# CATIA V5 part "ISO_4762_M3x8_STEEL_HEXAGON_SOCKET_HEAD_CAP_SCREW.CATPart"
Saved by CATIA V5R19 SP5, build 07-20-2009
Part number: ISO 4762 SCREW M3x8 STEEL HEXAGON SOCKET HEAD CAP
Publications: "Mating Face", "Axis"
Bounding box of the stored display mesh (mm): x -8 to 3, y -2.75 to 2.75, z -2.615 to 2.615
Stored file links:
  Z:\UA\ATLAS\atlascar\ServoPiloto\dir\suportePotenciometro\V2\potenciometro\ISO_4762_M3x8_STEEL_HEXAGON_SOCKET_HEAD_CAP_SCREW.CATPart
  Z:\programs_vbox\Dassault Systemes\B19\intel_a\startup\components\MechanicalStandardParts\EN_Standards\Design_Tables\EN_ISO_4762_HEXAGON_SOCKET_HEAD_CAP_SCREW.txt
  Z:\programs_vbox\Dassault Systemes\B19\intel_a\startup\components\MechanicalStandardParts\ISO_Standards\Design_Tables\ISO_4762_HEXAGON_SOCKET_HEAD_CAP_SCREW.txt
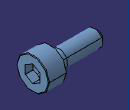
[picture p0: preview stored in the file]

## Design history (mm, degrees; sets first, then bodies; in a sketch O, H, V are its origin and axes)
Parameters
  d_dia = 3 mm
  l_nom = 8 mm
  k_head_depth_max = 3 mm
  s_nom = 2.5 mm
  r_min = 0.1 mm
  ds_max = 3 mm
  e = 2.873 mm
  t_min = 1.3 mm
  p_pitch = 0.5 mm
  Threading = 6.5 mm
  dk_max = 5.5 mm
Body1 "PartBody" (main body)
  Sketch1 on yz-plane, origin (0, 0, 0), H (0, 1, 0), V (0, 0, 1)
    circle A1 centre (0, 0) radius 2.75
    radius A1 = 2.75 {= dk_max /2}
  Pad1: profile Sketch1, direction (1, 0, 0), length 3 {= k_head_depth_max}
  Fillet1: radius 0.1 {= r_min}, on edge [face of Pad1 | face of Pad1]
  Body2
    Sketch2 on face of Pad1, origin (3, 0, 0), H (0, 1, 0), V (0, 0, 1)
      point P1 (1.25, -0.7217)
      point P2 (1.25, 0.7217)
      point P3 (0, 1.4434)
      point P4 (-1.25, 0.7217)
      point P5 (-1.25, -0.7217)
      point P6 (0, -1.4434)
      point P7 (1.25, 0)
      line L1 (1.25, -0.7217) -> (1.25, 0.7217)
      line L2 (1.25, 0.7217) -> (0, 1.4434)
      line L3 (0, 1.4434) -> (-1.25, 0.7217)
      line L4 (-1.25, 0.7217) -> (-1.25, -0.7217)
      line L5 (-1.25, -0.7217) -> (0, -1.4434)
      line L6 (0, -1.4434) -> (1.25, -0.7217)
      construction line L7 (0, 0) -> (1.25, 0)
      construction circle A1 centre (0, 0) radius 1.4434
      construction arc A2 centre (-1.25, -0.7217) radius 1.4434 from (-1.25, 0.7217) to (0, -1.4434) cw
      construction arc A3 centre (1.25, 0.7217) radius 1.4434 from (0, 1.4434) to (1.25, -0.7217) ccw
      point P8 (-1.25, -0.7217)
      point P9 (1.25, 0.7217)
      distance L1 L4 = 2.5 {= s_nom}
      horizontal: L7 H
      coincidence: A1 P1, A1 P2, A1 P3, A1 P4, A1 P5, A1 P6, A2 P4, A2 P6, A2 O, P8 P5, A3 P3, A3 P1, A3 O, P9 P2
      midpoint: P7 L1
    Pad2: profile Sketch2, direction (-1, 0, 0), length 2.128 {= t_min +(e /3.47)}
    Body3
      Sketch3 on zx-plane, origin (0, 0, 0), H (-1, 0, 0), V (0, 0, 1)
        point P1 (-0.8706, 0)
        line L1 (-0.8706, 0) -> (-1.7, 1.4365)
        line L2 (-1.7, 1.4365) -> (-3, 1.4365)
        line L3 (-3, 1.4365) -> (-3, 0)
        axis line L4 (-46.2384, 0) -> (26.3409, 0)
        reference projected line E1 (-3, -6.9227) -> (-3, 6.9227) from edge [face of Pad2 | face of Pad2]
        length L2 = 1.3 {= t_min}
        angle L1 L4 = 60
        distance L2 L4 = 1.4365 {= e /2}
        horizontal: L2 H, L4 H
        perpendicularity: L3 L2
        fix: L4
        coincidence: L3 E1, P1 L4
      Shaft1: profile Sketch3, axis Sketch3.L4, angle 360
    Intersect1: tool Body3
  Remove1: tool Body2
  Sketch4 on xy-plane, origin (0, 0, 0), H (1, 0, 0), V (0, 1, 0)
    line L1 (0, 0) -> (0, 1.5)
    line L2 (0, 1.5) -> (-1.5, 1.5)
    line L3 (-1.5, 1.5) -> (-1.5, 1.4634)
    line L4 (-1.5, 1.4634) -> (-8, 1.4634)
    line L5 (-8, 1.4634) -> (-8, 0)
    axis line L6 (-192.3446, 0) -> (99.1594, 0)
    distance L5 L1 = 8 {= l_nom}
    distance L3 L5 = 6.5 {= Threading}
    distance L2 L6 = 1.5 {= ds_max /2}
    distance L4 L6 = 1.4634 {= d_dia /2.05}
    vertical: L1 V, L3 V, L5 V
    horizontal: L2 H, L4 H, L6 H
    fix: L6
  Shaft2: profile Sketch4, axis Sketch4.L6, angle 360
  Fillet2: radius 0.1 {= r_min}, on edge [face of Shaft2 | face of Pad1]
  Chamfer1: length 0.5 {= p_pitch}, angle 45, on edge [face of Shaft2 | face of Shaft2]
  Thread1: diameter 2.9268 {= d_dia /1.025}, depth 6.5 {= Threading}, pitch 1, on face of Shaft2, from face of Shaft2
